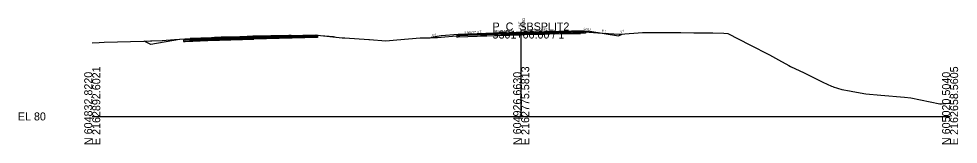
# Model space of a CAD drawing. Extents: x -26 to 1303, y -10 to 12033.
# Drawn here: x -25.7 to 302.8, y 10990.3 to 11034.1 of the extents above; entities that cross this region are included whole.
import ezdxf

# ---------------------------------------------------------------- set-up
doc = ezdxf.new("R2010")
doc.units = 0
for name, color, linetype in [('RD_GPK_XS_Cell', 7, 'Continuous'), ('RD_XS_Base', 7, 'Continuous'), ('RD_XS_ExGround', 7, 'Continuous'), ('RD_XS_ExPaveRet', 7, 'Continuous'), ('RD_XS_Greenside', 7, 'Continuous'), ('RD_XS_Pave', 7, 'Continuous'), ('RD_XS_PaveOvlay_CP', 7, 'Continuous'), ('RD_XS_TieSlope', 7, 'Continuous'), ('RD_XS_TX_Elev_EX', 7, 'Continuous'), ('RD_XS_TX_Elev_PR', 7, 'Continuous'), ('RD_XS_TX_ShdSlope', 7, 'Continuous'), ('RD_XS_TX_Slope', 7, 'Continuous')]:
    doc.layers.add(name, color=color, linetype=linetype)

msp = doc.modelspace()

# ---------------------------------------------------------------- linework, layer by layer
at = {"layer": 'RD_GPK_XS_Cell'}
for p, q in [((150, 11000), (150, 11030)), ((0, 11000), (150, 11000)), ((150, 11000), (300, 11000))]:
    msp.add_line(p, q, dxfattribs=at)
at = {"layer": 'RD_XS_Base'}
for p, q in [((150, 11028.98), (138, 11028.65)), ((150, 11028.98), (172, 11029.6)), ((150, 11028.48), (150, 11029.14)), ((150, 11029.14), (150, 11029.14)), ((150, 11029.14), (150, 11029.14)), ((150, 11029.14), (150, 11028.98)), ((172.5, 11029.11), (150, 11028.48)), ((150, 11028.98), (150, 11028.98)), ((150, 11028.48), (150, 11028.98)), ((150, 11028.98), (150, 11028.98)), ((150, 11028.98), (150, 11028.98)), ((162, 11029.32), (162, 11029.32)), ((162, 11029.32), (162, 11029.32)), ((172, 11029.6), (172, 11029.6)), ((172.5, 11029.61), (172.5, 11029.11)), ((172.5, 11029.58), (172.5, 11029.58)), ((32.29, 11026.68), (31.96, 11026.66)), ((31.96, 11026.66), (31.96, 11026.49)), ((31.96, 11026.49), (31.96, 11026.16)), ((31.96, 11026.16), (32.29, 11026.18)), ((32.46, 11026.68), (32.29, 11026.68)), ((32.29, 11026.18), (32.46, 11026.18)), ((40.46, 11027), (32.46, 11026.68)), ((32.46, 11026.18), (40.46, 11026.5)), ((44.46, 11027.16), (40.46, 11027)), ((40.46, 11026.5), (44.46, 11026.66)), ((52.55, 11027.37), (44.46, 11027.16)), ((44.46, 11026.66), (52.55, 11026.87)), ((56.46, 11027.47), (52.55, 11027.37)), ((52.55, 11026.87), (56.46, 11026.97)), ((56.46, 11027.47), (78.81, 11028.06)), ((56.46, 11026.97), (56.46, 11027.63)), ((56.46, 11027.63), (56.46, 11027.63)), ((56.46, 11027.63), (56.46, 11027.63)), ((56.46, 11027.63), (56.46, 11027.47)), ((78.81, 11027.56), (56.46, 11026.97)), ((56.46, 11027.47), (56.46, 11027.47)), ((56.46, 11026.97), (56.46, 11027.47)), ((56.46, 11027.47), (56.46, 11027.47)), ((56.46, 11027.47), (56.46, 11027.47)), ((56.46, 11026.97), (56.46, 11026.97)), ((78.31, 11028.04), (78.31, 11028.04)), ((78.81, 11028.06), (78.81, 11027.56)), ((78.81, 11028.02), (78.81, 11028.02)), ((128, 11028.25), (127.5, 11028.23)), ((127.5, 11028.23), (127.5, 11028.23)), ((127.5, 11028.23), (127.5, 11027.73)), ((127.5, 11027.73), (128, 11027.75)), ((138, 11028.65), (128, 11028.25)), ((128, 11028.25), (128, 11028.25)), ((128, 11027.75), (138, 11028.15)), ((128, 11027.75), (128, 11027.75)), ((136, 11028.57), (136, 11028.57)), ((136, 11028.07), (136, 11028.07)), ((138, 11028.15), (150, 11028.48)), ((150, 11028.48), (150, 11028.48)), ((162, 11028.82), (162, 11028.82)), ((162, 11028.82), (162, 11028.82))]:
    msp.add_line(p, q, dxfattribs=at)
at = {"layer": 'RD_XS_ExGround'}
msp.add_lwpolyline([(0, 11025.76), (2.36, 11025.86), (4.22, 11025.96), (18.05, 11026.32), (20.37, 11026.37), (20.86, 11026.39), (24.45, 11026.57), (28.8, 11026.84), (34.2, 11027.18), (42.94, 11027.55), (43.52, 11027.57), (43.99, 11027.59), (51.61, 11027.83), (54.15, 11027.96), (68.76, 11028.27), (69.56, 11028.29), (70.26, 11028.3), (70.34, 11028.3), (71.29, 11028.31), (73.67, 11028.37), (78.2, 11028.47), (79.77, 11028.29), (87.39, 11027.5), (88.34, 11027.5), (96.78, 11026.92), (97.01, 11026.91), (102.63, 11026.41), (106.48, 11026.8), (114.67, 11027.45), (115.18, 11027.46), (115.82, 11027.47), (118.22, 11027.49), (118.54, 11027.51), (119.43, 11027.52), (120.74, 11027.54), (128.54, 11028.22), (135.95, 11028.86), (137.69, 11028.95), (140.67, 11029.05), (145.65, 11029.21), (150.87, 11029.4), (151.25, 11029.41), (151.83, 11029.43), (156.47, 11029.46), (158.13, 11029.49), (159.99, 11029.58), (163.68, 11029.71), (170.7, 11029.69), (176.8, 11029.18), (184.23, 11028.68), (184.7, 11028.72), (192.43, 11029.28), (196.58, 11029.32), (203.55, 11029.29), (205.81, 11029.31), (210.39, 11029.19), (217.07, 11029.19), (220.83, 11029.06), (222.32, 11029.02), (229.95, 11024.98), (236.8, 11021.5), (239.96, 11019.71), (243.64, 11017.77), (244.23, 11017.47), (249, 11015.2), (250.78, 11014.3), (255.52, 11011.93), (258.58, 11010.57), (258.95, 11010.4), (259.1, 11010.35), (262.18, 11009.35), (264.79, 11008.9), (266.01, 11008.71), (270.56, 11007.89), (275.76, 11007.43), (284.05, 11006.74), (286.27, 11006.44), (296.39, 11004.42), (296.57, 11004.42), (297.04, 11004.45), (300, 11004.66)], dxfattribs=at)
at = {"layer": 'RD_XS_ExPaveRet'}
for points in [[(170.7, 11029.69), (170.7, 11029.69), (163.68, 11029.71), (163.68, 11029.71), (159.99, 11029.58), (159.99, 11029.58), (158.13, 11029.49), (158.13, 11029.49), (156.47, 11029.46), (156.47, 11029.46), (156.47, 11029.46), (151.83, 11029.43), (151.83, 11029.43), (151.25, 11029.41), (150.87, 11029.4), (150.87, 11029.4), (145.65, 11029.21), (145.65, 11029.21), (140.67, 11029.05), (137.69, 11028.95), (137.69, 11028.95), (137.69, 11028.95), (135.95, 11028.86), (135.95, 11028.86), (135.95, 11028.86), (135.95, 11028.86), (135.95, 11028.11), (135.95, 11028.11), (135.95, 11028.11), (137.69, 11028.2), (137.69, 11028.2), (137.69, 11028.2), (140.67, 11028.3), (145.65, 11028.46), (145.65, 11028.46), (150.87, 11028.65), (150.87, 11028.65), (151.25, 11028.66), (151.83, 11028.68), (151.83, 11028.68), (156.47, 11028.71), (156.47, 11028.71), (156.47, 11028.71), (158.13, 11028.74), (158.13, 11028.74), (159.99, 11028.83), (159.99, 11028.83), (163.68, 11028.96), (163.68, 11028.96), (170.7, 11028.94), (170.7, 11028.94), (170.7, 11028.94), (170.7, 11029.69), (170.7, 11029.69), (170.7, 11029.69)], [(170.7, 11029.69), (163.68, 11029.71), (159.99, 11029.58), (158.13, 11029.49), (156.47, 11029.46), (151.83, 11029.43), (151.25, 11029.41), (150.87, 11029.4), (145.65, 11029.21), (140.67, 11029.05), (137.69, 11028.95), (135.95, 11028.86), (135.95, 11028.11), (137.69, 11028.2), (140.67, 11028.3), (145.65, 11028.46), (150.87, 11028.65), (151.25, 11028.66), (151.83, 11028.68), (156.47, 11028.71), (158.13, 11028.74), (159.99, 11028.83), (163.68, 11028.96), (170.7, 11028.94), (170.7, 11028.94), (170.7, 11029.69), (170.7, 11029.69)], [(69.2, 11028.28), (69.55, 11028.29), (69.55, 11027.68), (69.55, 11027.54), (69.2, 11027.53), (68.76, 11027.52), (56.12, 11027.25), (54.15, 11027.21), (52.03, 11027.1), (51.61, 11027.08), (45.1, 11026.88), (44.31, 11026.85), (44.14, 11026.85), (43.53, 11026.82), (42.79, 11026.8), (41.75, 11026.75), (34.2, 11026.43), (34.2, 11026.43), (34.2, 11026.43), (34.2, 11026.43), (34.2, 11026.43), (34.2, 11026.51), (34.2, 11027.18), (34.2, 11027.18), (34.2, 11027.18), (34.2, 11027.18), (34.2, 11027.18), (41.75, 11027.5), (42.79, 11027.55), (43.53, 11027.57), (44.14, 11027.6), (44.31, 11027.6), (45.1, 11027.63), (51.61, 11027.83), (52.03, 11027.85), (54.15, 11027.96), (56.12, 11028), (68.76, 11028.27), (69.2, 11028.28)], [(68.76, 11028.27), (56.12, 11028), (54.15, 11027.96), (52.03, 11027.85), (51.61, 11027.83), (45.1, 11027.63), (44.31, 11027.6), (44.14, 11027.6), (43.53, 11027.57), (42.79, 11027.55), (41.75, 11027.5), (34.2, 11027.18), (34.2, 11027.18), (34.2, 11026.51), (34.2, 11026.43), (34.2, 11026.43), (41.75, 11026.75), (42.79, 11026.8), (43.53, 11026.82), (44.14, 11026.85), (44.31, 11026.85), (45.1, 11026.88), (51.61, 11027.08), (52.03, 11027.1), (54.15, 11027.21), (56.12, 11027.25), (68.76, 11027.52), (69.2, 11027.53), (69.55, 11027.54), (69.55, 11027.68), (69.55, 11028.29), (69.2, 11028.28), (68.76, 11028.27)]]:
    msp.add_lwpolyline(points, dxfattribs=at)
at = {"layer": 'RD_XS_Greenside'}
for p, q in [((174, 11029.76), (184, 11028.09)), ((20.46, 11025.17), (18.16, 11026.32)), ((30.46, 11026.84), (20.46, 11025.17)), ((84.31, 11027.88), (85.31, 11027.71)), ((122, 11028.09), (118.53, 11027.51)), ((184, 11028.09), (185.35, 11028.76))]:
    msp.add_line(p, q, dxfattribs=at)
at = {"layer": 'RD_XS_Pave'}
for p, q in [((138, 11028.97), (128, 11028.57)), ((136, 11028.89), (136, 11028.89)), ((150, 11029.3), (138, 11028.97)), ((138, 11028.81), (150, 11029.14)), ((150, 11029.14), (138, 11028.81)), ((138, 11028.65), (150, 11028.98)), ((172, 11029.92), (150, 11029.3)), ((172, 11029.76), (150, 11029.14)), ((150, 11029.14), (172, 11029.76)), ((150, 11028.98), (172.5, 11029.61)), ((150, 11029.3), (150, 11029.3)), ((150, 11029.14), (150, 11029.14)), ((150, 11029.14), (150, 11029.14)), ((150, 11029.14), (150, 11028.98)), ((150, 11029.14), (150, 11029.14)), ((150, 11028.98), (150, 11029.14)), ((150, 11029.14), (150, 11029.14)), ((150, 11029.14), (150, 11029.14)), ((150, 11028.98), (150, 11028.98)), ((150, 11028.98), (150, 11028.98)), ((162, 11029.64), (162, 11029.64)), ((162, 11029.64), (162, 11029.64)), ((162, 11029.48), (162, 11029.48)), ((162, 11029.48), (162, 11029.48)), ((162, 11029.48), (162, 11029.48)), ((162, 11029.48), (162, 11029.48)), ((162, 11029.32), (162, 11029.32)), ((162, 11029.32), (162, 11029.32)), ((172, 11029.76), (172, 11029.92)), ((172, 11029.92), (172, 11029.92)), ((172, 11029.6), (172, 11029.76)), ((172, 11029.76), (172, 11029.76)), ((40.46, 11027.32), (32.46, 11027)), ((32.46, 11026.84), (40.46, 11027.16)), ((40.46, 11027.16), (32.46, 11026.84)), ((32.46, 11027), (32.46, 11026.95)), ((32.46, 11026.68), (40.46, 11027)), ((32.46, 11026.95), (32.46, 11026.84)), ((32.46, 11026.84), (32.46, 11026.79)), ((32.46, 11026.79), (32.46, 11026.68)), ((44.46, 11027.48), (40.46, 11027.32)), ((40.46, 11027.16), (44.46, 11027.32)), ((44.46, 11027.32), (40.46, 11027.16)), ((40.46, 11027), (44.46, 11027.16)), ((52.55, 11027.69), (44.46, 11027.48)), ((44.46, 11027.32), (52.55, 11027.53)), ((52.55, 11027.53), (44.46, 11027.32)), ((44.46, 11027.16), (52.55, 11027.37)), ((56.46, 11027.79), (52.55, 11027.69)), ((52.55, 11027.53), (56.46, 11027.63)), ((56.46, 11027.63), (52.55, 11027.53)), ((52.55, 11027.37), (56.46, 11027.47)), ((78.31, 11028.36), (56.46, 11027.79)), ((78.31, 11028.2), (56.46, 11027.63)), ((56.46, 11027.63), (78.31, 11028.2)), ((56.46, 11027.47), (78.31, 11028.04)), ((56.46, 11027.79), (56.46, 11027.79)), ((56.46, 11027.63), (56.46, 11027.63)), ((56.46, 11027.63), (56.46, 11027.63)), ((56.46, 11027.63), (56.46, 11027.47)), ((56.46, 11027.63), (56.46, 11027.63)), ((56.46, 11027.47), (56.46, 11027.63)), ((56.46, 11027.63), (56.46, 11027.63)), ((56.46, 11027.63), (56.46, 11027.63)), ((56.46, 11027.47), (56.46, 11027.47)), ((56.46, 11027.47), (56.46, 11027.47)), ((78.31, 11028.2), (78.31, 11028.36)), ((78.31, 11028.36), (78.31, 11028.36)), ((78.31, 11028.04), (78.31, 11028.2)), ((78.31, 11028.2), (78.31, 11028.2)), ((128, 11028.41), (138, 11028.81)), ((138, 11028.81), (128, 11028.41)), ((128, 11028.25), (138, 11028.65)), ((128, 11028.57), (128, 11028.57)), ((128, 11028.57), (128, 11028.41)), ((128, 11028.41), (128, 11028.41)), ((128, 11028.41), (128, 11028.25)), ((136, 11028.73), (136, 11028.73)), ((136, 11028.73), (136, 11028.73)), ((136, 11028.57), (136, 11028.57))]:
    msp.add_line(p, q, dxfattribs=at)
at = {"layer": 'RD_XS_PaveOvlay_CP'}
for p, q in [((138, 11028.97), (128, 11028.57)), ((136, 11028.89), (136, 11028.89)), ((150, 11029.3), (138, 11028.97)), ((172, 11029.92), (150, 11029.3)), ((150, 11029.3), (150, 11029.3)), ((162, 11029.64), (162, 11029.64)), ((162, 11029.64), (162, 11029.64)), ((40.46, 11027.32), (32.46, 11027)), ((44.46, 11027.48), (40.46, 11027.32)), ((52.55, 11027.69), (44.46, 11027.48)), ((56.46, 11027.79), (52.55, 11027.69)), ((78.31, 11028.36), (56.46, 11027.79)), ((56.46, 11027.79), (56.46, 11027.79))]:
    msp.add_line(p, q, dxfattribs=at)
at = {"layer": 'RD_XS_TieSlope'}
for p, q in [((172, 11029.92), (174, 11029.76)), ((32.46, 11027), (30.46, 11026.84)), ((78.31, 11028.36), (84.31, 11027.88)), ((128, 11028.57), (122, 11028.09))]:
    msp.add_line(p, q, dxfattribs=at)

# ---------------------------------------------------------------- texts
at = {"layer": 'RD_GPK_XS_Cell'}
for s, p in [('P_C_SBSPLIT2', (140, 11030)), ('5301+00.00 / 1', (140, 11027.2)), ('EL 80', (-26, 10998.6))]:
    msp.add_text(s, height=2.8, dxfattribs=at).set_placement(p)
for s, p in [('E 2162892.6021', (2.8, 10990)), ('E 2162775.5813', (152.8, 10990)), ('E 2162658.5605', (302.8, 10990)), ('N 604832.8220', (0, 10990)), ('N 604926.6630', (150, 10990)), ('N 605020.5040', (300, 10990))]:
    msp.add_text(s, height=2.8, rotation=90, dxfattribs=at).set_placement(p)
at = {"layer": 'RD_XS_TX_Elev_EX'}
msp.add_text('109.37', height=0.6, rotation=90, dxfattribs=at).set_placement((149.76, 11030.56))
at = {"layer": 'RD_XS_TX_Elev_PR'}
msp.add_text('109.30', height=1, rotation=90, dxfattribs=at).set_placement((151.37, 11030.05))
at = {"layer": 'RD_XS_TX_ShdSlope'}
msp.add_text('12.5:1', height=0.75, rotation=355.4261, dxfattribs=at).set_placement((171.75, 11030.24))
at = {"layer": 'RD_XS_TX_Slope'}
for s, rotation, p in [('6:1', 9.4623, (118.95, 11027.99)), ('0.040 FT./FT.', 2.2906, (130.15, 11028.93)), ('0.030 FT./FT.', 1.7184, (141.04, 11029.31)), ('0.030 FT./FT.', 1.7184, (153.16, 11029.72)), ('6:1', 350.5358, (178.13, 11029.6)), ('2:1', 26.5651, (184.9, 11029.11))]:
    msp.add_text(s, height=0.75, rotation=rotation, dxfattribs=at).set_placement(p)

doc.saveas('drawing.dxf')
